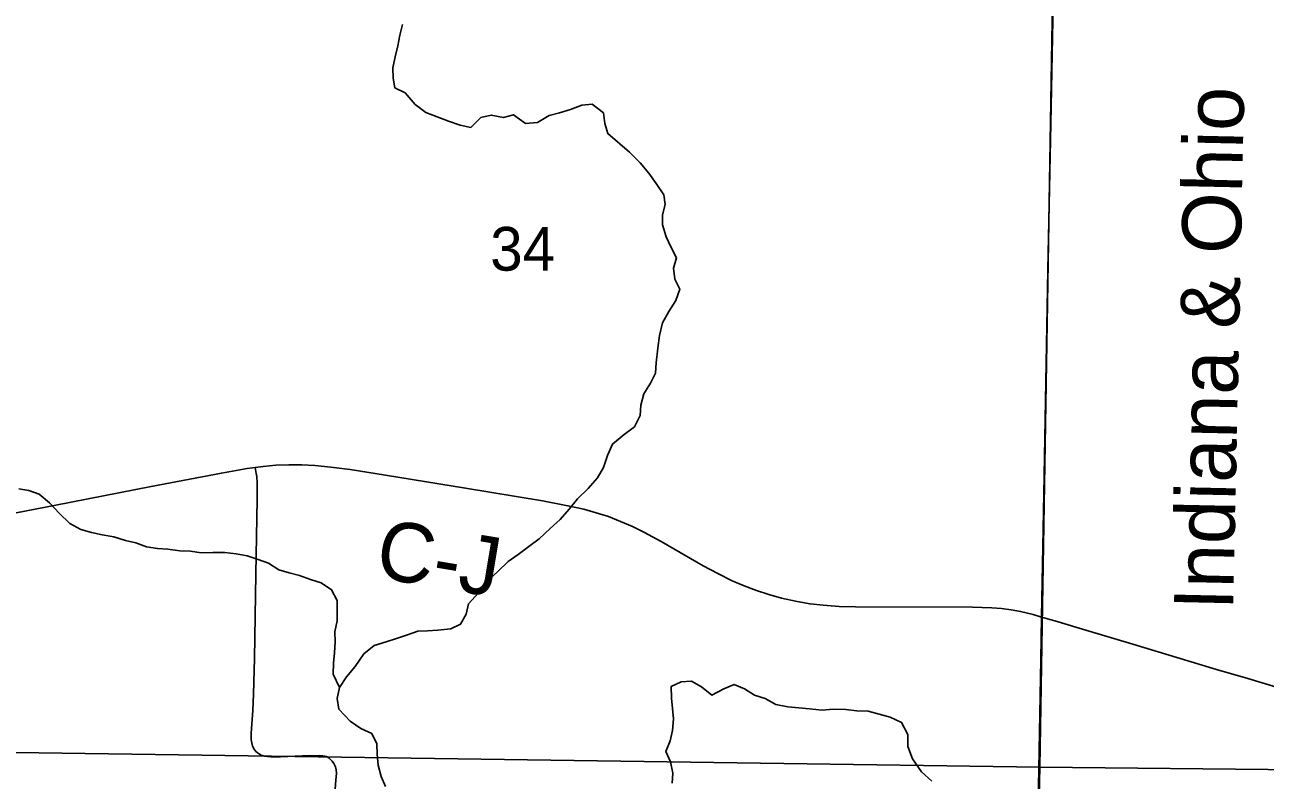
# Model space of a CAD drawing. Extents: x 0 to 42, y 0 to 22.
# Drawn here: x 3.302 to 4.49, y 19.512 to 20.235 of the extents above; entities that cross this region are included whole.
import ezdxf

# ---------------------------------------------------------------- set-up
doc = ezdxf.new("R2010")
doc.units = 0
for name, color, linetype in [('GM_X_County_Road', 7, 'Continuous'), ('GM_X_County_Road_Text', 7, 'Continuous'), ('GM_X_Minor_River', 7, 'Continuous'), ('GM_X_Rail_Line_Text', 7, 'Continuous'), ('GM_X_Section', 7, 'Continuous'), ('GM_X_Section_Text', 7, 'Continuous'), ('GM_X_State_Route', 7, 'Continuous'), ('GM_X_Township_Road', 7, 'Continuous')]:
    doc.layers.add(name, color=color, linetype=linetype)

msp = doc.modelspace()

# ---------------------------------------------------------------- linework, layer by layer
at = {"layer": 'GM_X_County_Road'}
for points in [[(3.2733, 19.7638), (3.3314, 19.775), (3.4229, 19.793), (3.4901, 19.8058), (3.5146, 19.8101), (3.5224, 19.8111)], [(3.5224, 19.8111), (3.53, 19.8122), (3.5423, 19.8133), (3.5547, 19.8138), (3.5671, 19.8138), (3.5795, 19.8131), (3.5949, 19.8116), (3.6134, 19.8092), (3.6471, 19.8038), (3.7239, 19.7915), (3.7975, 19.7791), (3.8219, 19.7746), (3.8371, 19.7712), (3.849, 19.7679), (3.8608, 19.7641), (3.8723, 19.7596), (3.8837, 19.7546), (3.8948, 19.7491), (3.9112, 19.7402), (3.9516, 19.717), (3.9654, 19.7097), (3.9794, 19.7028), (3.9908, 19.6979), (4.0025, 19.6934), (4.0144, 19.6896), (4.0264, 19.6862), (4.0416, 19.6828), (4.0539, 19.6806), (4.0663, 19.6792), (4.0819, 19.6782), (4.0974, 19.6777), (4.2094, 19.6774), (4.228, 19.6769), (4.2372, 19.6762), (4.2464, 19.675), (4.2555, 19.6733), (4.2675, 19.6704), (4.2757, 19.668)], [(4.2757, 19.668), (4.2884, 19.6643), (4.3212, 19.6545), (4.3599, 19.6429), (4.4433, 19.6177), (4.4731, 19.609), (4.5177, 19.5956), (4.634, 19.5613), (4.6512, 19.5561)]]:
    msp.add_lwpolyline(points, dxfattribs=at)
at = {"layer": 'GM_X_Minor_River'}
for points in [[(3.6634, 20.2354), (3.6609, 20.2252), (3.6591, 20.215), (3.6566, 20.2044), (3.6544, 20.1939), (3.6546, 20.184), (3.6562, 20.1745), (3.666, 20.1697), (3.6756, 20.1588), (3.686, 20.151), (3.6966, 20.147), (3.7075, 20.1426), (3.7188, 20.1389), (3.729, 20.1368), (3.7387, 20.1464), (3.7486, 20.1485), (3.7603, 20.1463), (3.7698, 20.1488), (3.7814, 20.1405), (3.7928, 20.1414), (3.804, 20.148), (3.8139, 20.1508), (3.8246, 20.154), (3.8353, 20.1579), (3.8452, 20.1589), (3.856, 20.1506), (3.8573, 20.1404), (3.8601, 20.1308), (3.8809, 20.1129), (3.8913, 20.1028), (3.8994, 20.0931), (3.9064, 20.0831), (3.9137, 20.0723), (3.915, 20.0628), (3.9125, 20.053), (3.9127, 20.0435), (3.9162, 20.032), (3.9205, 20.0224), (3.926, 20.012), (3.9231, 20.0019), (3.9243, 19.9916), (3.9291, 19.982), (3.9254, 19.9711), (3.9187, 19.9606), (3.9127, 19.9497), (3.9098, 19.9376), (3.908, 19.9255), (3.9065, 19.9115), (3.9059, 19.9016), (3.9011, 19.8919), (3.8948, 19.8818), (3.8919, 19.8708), (3.8913, 19.861), (3.8857, 19.8501), (3.8757, 19.8427), (3.8648, 19.8335), (3.86, 19.8226), (3.856, 19.8113), (3.8504, 19.8012), (3.8415, 19.7911), (3.831, 19.7811), (3.8232, 19.7714), (3.8146, 19.7613), (3.8049, 19.7528), (3.7944, 19.7428), (3.7844, 19.7354), (3.7743, 19.7277), (3.7647, 19.7211), (3.7546, 19.7114), (3.7449, 19.7025), (3.7363, 19.6913), (3.7269, 19.6805), (3.7244, 19.6707), (3.7192, 19.661), (3.7097, 19.6566), (3.6975, 19.6554), (3.6876, 19.6548), (3.6781, 19.6543), (3.6682, 19.6511), (3.6578, 19.6475), (3.6479, 19.6443), (3.6364, 19.6408), (3.6264, 19.6327), (3.6181, 19.6207), (3.6099, 19.6106), (3.6032, 19.6005)], [(3.6032, 19.6005), (3.5971, 19.6132), (3.5973, 19.6238), (3.5983, 19.6337), (3.599, 19.6443), (3.5988, 19.6538), (3.601, 19.6644), (3.6008, 19.6742), (3.601, 19.6837), (3.5956, 19.6941), (3.5855, 19.7008), (3.5753, 19.704), (3.5648, 19.7077), (3.555, 19.7102), (3.5452, 19.7131), (3.5351, 19.7197), (3.5253, 19.723), (3.5148, 19.7266), (3.5042, 19.7284), (3.4932, 19.7298), (3.4818, 19.7297), (3.4708, 19.7295), (3.4606, 19.7309), (3.4504, 19.7315), (3.4387, 19.7329), (3.4288, 19.7335), (3.4182, 19.7352), (3.4081, 19.7389), (3.3983, 19.7414), (3.387, 19.7447), (3.376, 19.7468), (3.3658, 19.7489), (3.3553, 19.7518), (3.3448, 19.7574), (3.3348, 19.7675), (3.3255, 19.7772), (3.3155, 19.7857), (3.3057, 19.789), (3.2959, 19.7907)], [(3.9217, 19.5088), (3.9223, 19.5186), (3.9203, 19.5293), (3.9159, 19.5393), (3.92, 19.5494), (3.9221, 19.5593), (3.9231, 19.5706), (3.9213, 19.5904), (3.9208, 19.6014), (3.9304, 19.6061), (3.9403, 19.6067), (3.95, 19.6012), (3.9597, 19.5933), (3.9712, 19.5992), (3.9812, 19.6035), (3.991, 19.5991), (4.0007, 19.5932), (4.0109, 19.5899), (4.021, 19.5844), (4.0327, 19.5819), (4.0433, 19.5812), (4.0535, 19.5802), (4.0656, 19.5788), (4.0759, 19.5797), (4.088, 19.5795), (4.0986, 19.5781), (4.1096, 19.5779), (4.1307, 19.5721), (4.1416, 19.5669), (4.1474, 19.5554), (4.1475, 19.544), (4.1521, 19.5321), (4.1606, 19.5198), (4.1706, 19.5108)], [(3.6032, 19.6005), (3.6011, 19.59), (3.6027, 19.5797), (3.6135, 19.5684), (3.6236, 19.5614), (3.6341, 19.5566), (3.6388, 19.5466), (3.6393, 19.5367), (3.6402, 19.5261), (3.643, 19.5154), (3.6473, 19.5058)]]:
    msp.add_lwpolyline(points, dxfattribs=at)
at = {"layer": 'GM_X_Section'}
for points in [[(3.2881, 20.5445), (4.2905, 20.5288), (4.2741, 19.5242), (3.2701, 19.5386)], [(4.2905, 20.5288), (5.2947, 20.5242), (5.2809, 19.5139), (5.2739, 19.514), (4.2741, 19.5242)], [(4.2741, 19.5242), (4.2501, 18.4923), (3.2549, 18.4906), (3.2701, 19.5386)], [(5.2524, 18.4847), (4.2501, 18.4923), (4.2741, 19.5242), (5.2739, 19.514)]]:
    msp.add_lwpolyline(points, close=True, dxfattribs=at)
at = {"layer": 'GM_X_State_Route'}
msp.add_lwpolyline([(4.2602, 19.0384), (4.261, 19.0526), (4.2655, 19.1396), (4.2679, 19.2173), (4.2689, 19.2919), (4.2697, 19.3479), (4.2708, 19.3977), (4.2718, 19.453), (4.2749, 19.6272), (4.2757, 19.668), (4.2779, 19.7858), (4.2816, 20.0004), (4.2845, 20.1404), (4.2874, 20.2896)], dxfattribs=at)
at = {"layer": 'GM_X_Township_Road'}
for points in [[(3.2733, 19.7638), (3.3314, 19.775), (3.4229, 19.793), (3.4901, 19.8058), (3.5146, 19.8101), (3.5224, 19.8111)], [(3.5977, 19.4842), (3.5998, 19.5122), (3.6003, 19.5182), (3.6, 19.5217), (3.5993, 19.5246), (3.5977, 19.5279), (3.5962, 19.5299), (3.5937, 19.5325), (3.592, 19.5337), (3.5908, 19.5344), (3.5891, 19.5348), (3.5873, 19.535), (3.5842, 19.5353), (3.5811, 19.5352), (3.5748, 19.5353), (3.5468, 19.534), (3.5374, 19.534), (3.5343, 19.5343), (3.5313, 19.5349), (3.5283, 19.5358), (3.5256, 19.5373), (3.5232, 19.5393), (3.5213, 19.5416), (3.5199, 19.5444), (3.5191, 19.5474), (3.5186, 19.5505), (3.5185, 19.5536), (3.5186, 19.5567), (3.5202, 19.5785), (3.5209, 19.594), (3.5217, 19.6282), (3.523, 19.7091), (3.5242, 19.7807), (3.5244, 19.7963), (3.5239, 19.8025), (3.5234, 19.8055), (3.5224, 19.8111)], [(3.5224, 19.8111), (3.53, 19.8122), (3.5423, 19.8133), (3.5547, 19.8138), (3.5671, 19.8138), (3.5795, 19.8131), (3.5949, 19.8116), (3.6134, 19.8092), (3.6471, 19.8038), (3.7239, 19.7915), (3.7975, 19.7791), (3.8219, 19.7746), (3.8371, 19.7712), (3.849, 19.7679), (3.8608, 19.7641), (3.8723, 19.7596), (3.8837, 19.7546), (3.8948, 19.7491), (3.9112, 19.7402), (3.9516, 19.717), (3.9654, 19.7097), (3.9794, 19.7028), (3.9908, 19.6979), (4.0025, 19.6934), (4.0144, 19.6896), (4.0264, 19.6862), (4.0416, 19.6828), (4.0539, 19.6806), (4.0663, 19.6792), (4.0819, 19.6782), (4.0974, 19.6777), (4.2094, 19.6774), (4.228, 19.6769), (4.2372, 19.6762), (4.2464, 19.675), (4.2555, 19.6733), (4.2675, 19.6704), (4.2757, 19.668)], [(4.2757, 19.668), (4.2884, 19.6643), (4.3212, 19.6545), (4.3599, 19.6429), (4.4433, 19.6177), (4.4731, 19.609), (4.5177, 19.5956), (4.634, 19.5613), (4.6512, 19.5561)]]:
    msp.add_lwpolyline(points, dxfattribs=at)

# ---------------------------------------------------------------- texts
at = {"layer": 'GM_X_County_Road_Text'}
msp.add_text('C-J', height=0.05682, rotation=350.5374, dxfattribs=at).set_placement((3.6358, 19.7063))
at = {"layer": 'GM_X_Rail_Line_Text'}
msp.add_text('Indiana & Ohio', height=0.056629, rotation=88.7669, dxfattribs=at).set_placement((4.459, 19.6742))
at = {"layer": 'GM_X_Section_Text'}
msp.add_text('34', height=0.04186, rotation=0, dxfattribs=at).set_placement((3.7475, 19.9996))

doc.saveas('drawing.dxf')
